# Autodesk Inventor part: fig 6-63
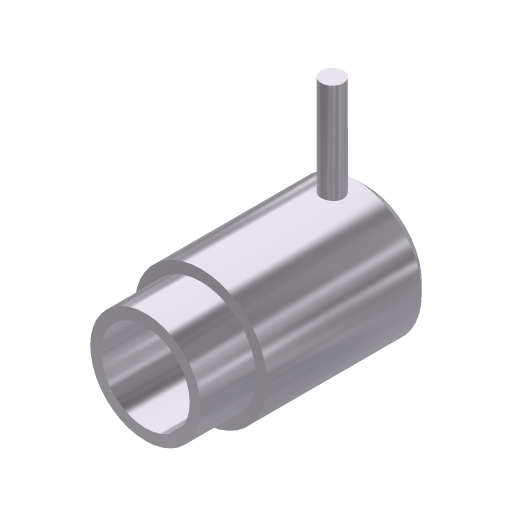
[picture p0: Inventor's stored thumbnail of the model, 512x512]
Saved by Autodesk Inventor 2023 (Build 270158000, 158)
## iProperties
Created: 2001-12
Part Number: fig 6-63
Document SubType Name: Modeling
Designer: Renu Muthoo
Density: 1 g/cm^3
Material: Generic
Appearance: Metal-AL-6061 (Polished)
Control State: 0
Master: False
Checked Out: False
Shininess: 77.0
Angle Display Precision: 2
Document Length Units: 11269
Document Angle Units: 11279
Document Time Units: 11290
Document Mass Units: 11283
Document Length Units Precision: 3
Document Angle Units Precision: 2
Compacted: True
Density: 0.0
Volumn: 0.0
Area: 0.0
PropertySet Name: Model Information
Author: Renu Muthoo
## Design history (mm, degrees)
sketch "Sketch2"
  geometry: L1 (-9.573, -4.327)-(-9.573, -5.327); L2 (-9.573, -5.327)-(-4.573, -5.327); L3 (-4.573, -5.327)-(-4.573, -6.327); L4 (-4.573, -6.327)-(9.427, -6.327); L5 (9.427, -6.327)-(10.427, -5.327); L6 (10.427, -5.327)-(10.427, -4.327); L7 (10.427, -4.327)-(-9.573, -4.327); L8 (-13.687, -0.327)-(14, -0.327)
  constraints: 16 end point, 5 parallel, 1 perpendicular, 1 vertical
  dimensions: "d9" = 20 distance of L6.end L1.start; "d10" = 5 distance of L1.end L2.end; "d11" = 12 diameter of L4 L8; "d12" = 10 diameter of L2 L8; "d13" = 8 diameter of L7 L8; "d14" = 45 deg angle of L5 L4; "d15" = 1 horizontal distance of L5.end L4.end
revolve "Revolution2" sketch "Sketch2" stored, may be unused: angle "d16" = 90 deg
workplane "Work Plane1"
workplane "Work Plane2"
sketch "Sketch3"
  geometry: L1 (-4, 8)-(4, 8) reference; C1 r 1 at (-0.098, 5)
  constraints: 1 centre point
  dimensions: "d18" = 3 distance from line of L1 C1.centre; "d19" = 2 diameter of C1
extrude "Extrusion1" join sketch "Sketch3" distance "d20" = 10; taper "d21" = 0 deg
body "Solid1"
other parameters: "d17" = -1
